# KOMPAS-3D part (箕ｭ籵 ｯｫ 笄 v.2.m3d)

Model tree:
1. Эскиз:1
2. Операция выдавливания:1
     Расстояние 1 = 2
3. Эскиз:2
4. Вырезать элемент выдавливания:2  (labels: Текстолит ГОСТ 5-78; SYSTEM_PROPERTY_ADDITIONAL_FOR:9.000000)
     Расстояние 1 = 2

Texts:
  Центр плата v.2 верх
  Текстолит ГОСТ 5-78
